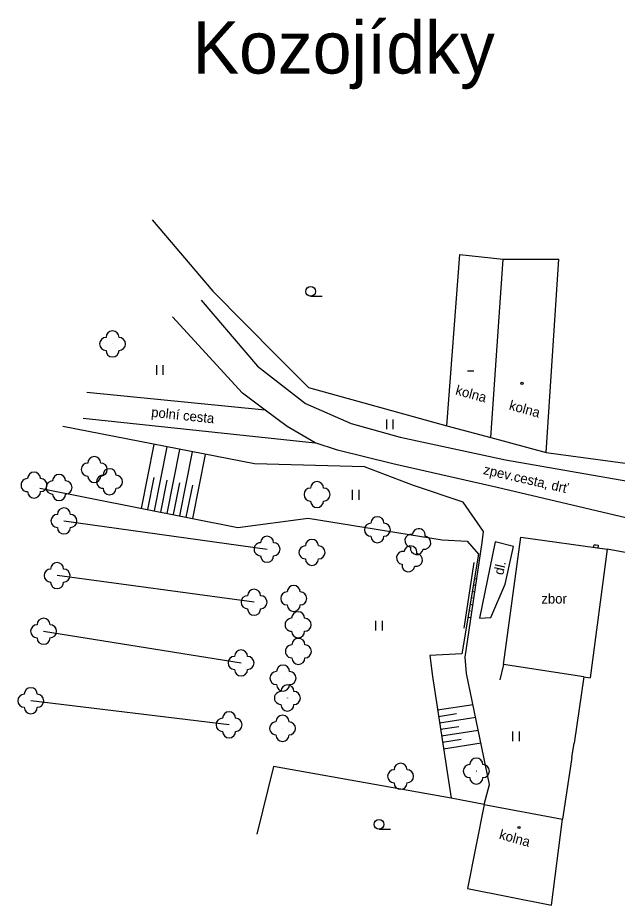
# Model space of a CAD drawing. Extents: x -544674 to -541478, y -1199076 to -1195527.
# Drawn here: x -543930.8 to -543884.8, y -1197382.1 to -1197313.9 of the extents above; entities that cross this region are included whole.
import ezdxf

# ---------------------------------------------------------------- set-up
doc = ezdxf.new("R2010")
doc.units = 0
for name, color, linetype in [('BUDOVY_MĚŘ', 7, 'Continuous'), ('BUDOVY_NEMĚŘ', 7, 'Continuous'), ('NÁZVY_SÍDEL_JEDNOTKY', 7, 'Continuous'), ('OBVOD_PILÍŘE', 7, 'Continuous'), ('POMOC_POPIS', 7, 'Continuous'), ('ROZHRANÍ_PLOCH', 7, 'Continuous'), ('VÝŠKOPIS', 7, 'Continuous'), ('ZELEŇ', 7, 'Continuous'), ('ZN_BUDOV', 7, 'Continuous'), ('ZN_DOPLŇKOVÉ', 7, 'Continuous'), ('ZN_KULTUR', 7, 'Continuous')]:
    doc.layers.add(name, color=color, linetype=linetype)

msp = doc.modelspace()

# ---------------------------------------------------------------- linework, layer by layer
at = {"layer": 'BUDOVY_MĚŘ'}
for points in [[(-543897.87, -1197345.26), (-543894.49, -1197346.15)], [(-543894.49, -1197346.15), (-543890.24, -1197347.31)], [(-543893.51, -1197363.58), (-543892.19, -1197353.8), (-543885.56, -1197354.73)], [(-543885.56, -1197354.73), (-543886.86, -1197364.61)], [(-543887.36, -1197364.53), (-543893.51, -1197363.58)], [(-543887.36, -1197364.53), (-543886.86, -1197364.61)], [(-543895.01, -1197374.32), (-543888.98, -1197375.44)]]:
    msp.add_lwpolyline(points, dxfattribs=at)
at = {"layer": 'BUDOVY_NEMĚŘ'}
for points in [[(-543897.87, -1197345.26), (-543896.87, -1197332.11)], [(-543896.87, -1197332.11), (-543893.55, -1197332.47)], [(-543894.49, -1197346.15), (-543893.55, -1197332.47)], [(-543893.55, -1197332.47), (-543889.26, -1197332.45)], [(-543890.24, -1197347.31), (-543889.26, -1197332.45)], [(-543895.01, -1197374.32), (-543896.29, -1197380.78), (-543889.83, -1197382.06), (-543888.98, -1197375.44)]]:
    msp.add_lwpolyline(points, dxfattribs=at)
at = {"layer": 'OBVOD_PILÍŘE'}
msp.add_lwpolyline([(-543886.41, -1197354.4), (-543886.25, -1197354.42), (-543886.28, -1197354.64), (-543886.6, -1197354.6), (-543886.57, -1197354.38), (-543886.41, -1197354.4)], dxfattribs=at)
at = {"layer": 'ROZHRANÍ_PLOCH'}
for points in [[(-543916.72, -1197335.6), (-543912.4, -1197340.67), (-543908.7, -1197343.54), (-543905.2, -1197345.09), (-543901.45, -1197346.13), (-543893.37, -1197347.87), (-543883.39, -1197349.61), (-543879.4, -1197350.37)], [(-543911.81, -1197344.06), (-543913.54, -1197342.76), (-543918.9, -1197336.89)], [(-543911.81, -1197344.06), (-543925.49, -1197342.71)], [(-543907.96, -1197346.55), (-543910.11, -1197345.31), (-543911.81, -1197344.06)], [(-543925.75, -1197344.68), (-543907.96, -1197346.55)], [(-543879.77, -1197353.15), (-543883.7, -1197352.41), (-543893.99, -1197349.99), (-543902.01, -1197348.18), (-543906.24, -1197347.12), (-543907.96, -1197346.55)], [(-543895.37, -1197360.02), (-543894.48, -1197359.97), (-543893.4, -1197357.42), (-543892.75, -1197354.51), (-543894.16, -1197354.17), (-543895.37, -1197360.02)]]:
    msp.add_lwpolyline(points, dxfattribs=at)
at = {"layer": 'VÝŠKOPIS'}
for points in [[(-543895.01, -1197374.32), (-543894.58, -1197372.78), (-543896.35, -1197364.26), (-543896.46, -1197363.02), (-543895.16, -1197354.2), (-543895.04, -1197353.37), (-543896.61, -1197351.11), (-543900.41, -1197349.84), (-543904.19, -1197348.41), (-543912.63, -1197348.18), (-543927.31, -1197345.32)], [(-543921.28, -1197351.59), (-543920.31, -1197346.68)], [(-543920.3, -1197351.78), (-543919.33, -1197346.88)], [(-543919.32, -1197351.98), (-543918.35, -1197347.07)], [(-543918.34, -1197352.17), (-543917.37, -1197347.26)], [(-543917.36, -1197352.36), (-543916.38, -1197347.45)], [(-543920.79, -1197351.68), (-543920.31, -1197349.23)], [(-543929.08, -1197350.04), (-543913.9, -1197353.05), (-543908.51, -1197352.34), (-543898.22, -1197354.01), (-543896.31, -1197354.12), (-543895.44, -1197355.11), (-543896.71, -1197362.76), (-543899.18, -1197362.88), (-543898.97, -1197364.51), (-543897.53, -1197373.85)], [(-543919.81, -1197351.88), (-543919.33, -1197349.42)], [(-543918.83, -1197352.07), (-543918.34, -1197349.62)], [(-543917.85, -1197352.27), (-543917.36, -1197349.81)], [(-543895.83, -1197357.47), (-543895.74, -1197357.49)], [(-543895.75, -1197356.98), (-543895.57, -1197357.01)], [(-543895.91, -1197357.96), (-543895.72, -1197358)], [(-543896, -1197358.46), (-543895.89, -1197358.47)], [(-543896.16, -1197359.44), (-543896.05, -1197359.46)], [(-543896.08, -1197358.95), (-543895.86, -1197358.99)], [(-543896.24, -1197359.94), (-543896.01, -1197359.97)], [(-543898.57, -1197367.07), (-543895.85, -1197366.65)], [(-543898.5, -1197367.56), (-543897.12, -1197367.35)], [(-543898.42, -1197368.06), (-543895.65, -1197367.63)], [(-543898.35, -1197368.55), (-543896.95, -1197368.34)], [(-543898.27, -1197369.05), (-543895.45, -1197368.61)], [(-543898.19, -1197369.54), (-543896.77, -1197369.32)], [(-543898.12, -1197370.04), (-543895.24, -1197369.59)]]:
    msp.add_lwpolyline(points, dxfattribs=at)
at = {"layer": 'ZELEŇ'}
for points in [[(-543927.24, -1197352.56), (-543911.65, -1197354.73)], [(-543912.65, -1197358.8), (-543927.76, -1197356.75)], [(-543928.8, -1197361.03), (-543913.65, -1197363.46)], [(-543914.57, -1197368.21), (-543929.78, -1197366.36)]]:
    msp.add_lwpolyline(points, dxfattribs=at)
for centre in [(-543923.51, -1197338.97), (-543924.91, -1197348.61), (-543929.53, -1197349.81), (-543927.61, -1197349.99), (-543923.74, -1197349.55), (-543907.82, -1197350.53), (-543927.24, -1197352.56), (-543903.19, -1197353.23), (-543900.09, -1197354.15), (-543911.65, -1197354.73), (-543908.21, -1197354.97), (-543900.73, -1197355.47), (-543927.76, -1197356.75), (-543912.65, -1197358.8), (-543909.61, -1197358.51), (-543909.27, -1197360.53), (-543928.8, -1197361.03), (-543909.25, -1197362.57), (-543913.65, -1197363.46), (-543910.43, -1197364.62), (-543929.78, -1197366.36), (-543910.09, -1197366.15), (-543914.57, -1197368.21), (-543910.47, -1197368.48), (-543895.6, -1197371.76), (-543901.41, -1197372.16)]:
    msp.add_circle(centre, 0.0005, dxfattribs=at)
for centre, start, end in [((-543924.01, -1197338.97), 89.99999, 269.99999), ((-543923.51, -1197338.47), 0, 179.99999), ((-543923.01, -1197338.97), 270, 89.99999), ((-543923.51, -1197339.47), 179.99999, 359.99999), ((-543924.91, -1197348.11), 360, 179.99999), ((-543925.41, -1197348.61), 90, 269.99999), ((-543924.41, -1197348.61), 270, 90), ((-543923.74, -1197349.05), 359.99998, 179.99998), ((-543930.03, -1197349.81), 89.99998, 269.99998), ((-543929.53, -1197349.31), 359.99998, 179.99998), ((-543929.03, -1197349.81), 269.99998, 89.99997), ((-543927.61, -1197349.49), 360, 179.99999), ((-543924.91, -1197349.11), 180, 360), ((-543924.24, -1197349.55), 89.99998, 269.99998), ((-543923.24, -1197349.55), 269.99998, 89.99997), ((-543928.11, -1197349.99), 90, 269.99999), ((-543927.11, -1197349.99), 270, 90), ((-543923.74, -1197350.05), 179.99998, 359.99997), ((-543908.32, -1197350.53), 89.99999, 269.99999), ((-543907.82, -1197350.03), 0, 179.99999), ((-543907.32, -1197350.53), 270, 89.99999), ((-543929.53, -1197350.31), 179.99998, 359.99997), ((-543927.61, -1197350.49), 180, 360), ((-543907.82, -1197351.03), 179.99999, 359.99999), ((-543927.74, -1197352.56), 90, 269.99999), ((-543927.24, -1197352.06), 360, 179.99999), ((-543926.74, -1197352.56), 270, 90), ((-543903.69, -1197353.23), 90, 269.99999), ((-543903.19, -1197352.73), 360, 179.99999), ((-543902.69, -1197353.23), 270, 90), ((-543927.24, -1197353.06), 180, 360), ((-543900.012, -1197353.656), 351.04001, 171.04001), ((-543911.65, -1197354.23), 359.99998, 179.99998), ((-543908.21, -1197354.47), 359.99998, 179.99998), ((-543903.19, -1197353.73), 180, 360), ((-543900.584, -1197354.072), 81.04001, 261.04), ((-543899.596, -1197354.228), 261.04001, 81.04001), ((-543912.15, -1197354.73), 89.99998, 269.99998), ((-543911.15, -1197354.73), 269.99998, 89.99997), ((-543908.71, -1197354.97), 89.99998, 269.99998), ((-543907.71, -1197354.97), 269.99998, 89.99997), ((-543900.652, -1197354.976), 351.04001, 171.04001), ((-543900.168, -1197354.644), 171.04001, 351.04), ((-543911.65, -1197355.23), 179.99998, 359.99997), ((-543908.21, -1197355.47), 179.99998, 359.99997), ((-543901.224, -1197355.392), 81.04001, 261.04), ((-543900.236, -1197355.548), 261.04001, 81.04001), ((-543927.76, -1197356.25), 360, 179.99999), ((-543900.808, -1197355.964), 171.04001, 351.04), ((-543928.26, -1197356.75), 90, 269.99999), ((-543927.26, -1197356.75), 270, 90), ((-543927.76, -1197357.25), 180, 360), ((-543909.61, -1197358.01), 360, 179.99999), ((-543912.65, -1197358.3), 360, 179.99999), ((-543910.11, -1197358.51), 90, 269.99999), ((-543909.11, -1197358.51), 270, 90), ((-543913.15, -1197358.8), 90, 269.99999), ((-543912.15, -1197358.8), 270, 90), ((-543912.65, -1197359.3), 180, 360), ((-543909.61, -1197359.01), 180, 360), ((-543909.27, -1197360.03), 359.99998, 179.99998), ((-543928.8, -1197360.53), 360, 179.99999), ((-543909.77, -1197360.53), 89.99998, 269.99998), ((-543908.77, -1197360.53), 269.99998, 89.99997), ((-543929.3, -1197361.03), 90, 269.99999), ((-543928.3, -1197361.03), 270, 90), ((-543928.8, -1197361.53), 180, 360), ((-543909.27, -1197361.03), 179.99998, 359.99997), ((-543909.25, -1197362.07), 359.99998, 179.99998), ((-543909.75, -1197362.57), 89.99998, 269.99998), ((-543908.75, -1197362.57), 269.99998, 89.99997), ((-543914.15, -1197363.46), 90, 269.99999), ((-543913.65, -1197362.96), 360, 179.99999), ((-543913.15, -1197363.46), 270, 90), ((-543910.43, -1197364.12), 360, 179.99999), ((-543909.25, -1197363.07), 179.99998, 359.99997), ((-543913.65, -1197363.96), 180, 360), ((-543910.93, -1197364.62), 90, 269.99999), ((-543909.93, -1197364.62), 270, 90), ((-543929.78, -1197365.86), 360, 179.99999), ((-543910.59, -1197366.15), 89.99998, 269.99998), ((-543910.43, -1197365.12), 180, 360), ((-543910.09, -1197365.65), 359.99998, 179.99998), ((-543909.59, -1197366.15), 269.99998, 89.99997), ((-543930.28, -1197366.36), 90, 269.99999), ((-543929.28, -1197366.36), 270, 90), ((-543929.78, -1197366.86), 180, 360), ((-543910.09, -1197366.65), 179.99998, 359.99997), ((-543915.07, -1197368.21), 89.99999, 269.99999), ((-543914.57, -1197367.71), 0, 179.99999), ((-543914.07, -1197368.21), 270, 89.99999), ((-543910.47, -1197367.98), 359.99998, 179.99998), ((-543910.97, -1197368.48), 89.99998, 269.99998), ((-543909.97, -1197368.48), 269.99998, 89.99997), ((-543914.57, -1197368.71), 179.99999, 359.99999), ((-543910.47, -1197368.98), 179.99998, 359.99997), ((-543901.41, -1197371.66), 360, 179.99999), ((-543895.6, -1197371.26), 360, 179.99999), ((-543901.91, -1197372.16), 90, 269.99999), ((-543900.91, -1197372.16), 270, 90), ((-543896.1, -1197371.76), 90, 269.99999), ((-543895.1, -1197371.76), 270, 90), ((-543895.6, -1197372.26), 180, 360), ((-543901.41, -1197372.66), 180, 360)]:
    msp.add_arc(centre, 0.5, start, end, dxfattribs=at)
at = {"layer": 'ZN_BUDOV'}
msp.add_line((-543896.28, -1197341.03), (-543895.78, -1197341.03), dxfattribs=at)
for centre in [(-543892.09, -1197341.99), (-543892.33, -1197376.09)]:
    msp.add_circle(centre, 0.0875, dxfattribs=at)
at = {"layer": 'ZN_DOPLŇKOVÉ'}
for points in [[(-543920.48, -1197329.44), (-543915.81, -1197334.92), (-543910.89, -1197339.9)], [(-543910.89, -1197339.9), (-543908.48, -1197342.32)], [(-543908.48, -1197342.32), (-543897.87, -1197345.26)], [(-543890.24, -1197347.31), (-543882.3, -1197348.39), (-543874.25, -1197349.54)], [(-543882.93, -1197355.22), (-543885.56, -1197354.73)], [(-543896.53, -1197360.78), (-543895.76, -1197355.75)], [(-543893.51, -1197363.58), (-543893.8, -1197364.76)], [(-543887.36, -1197364.53), (-543888.09, -1197369.63)], [(-543888.28, -1197370.72), (-543888.09, -1197369.63)], [(-543888.28, -1197370.72), (-543888.98, -1197375.44)], [(-543897.53, -1197373.85), (-543911.16, -1197371.4), (-543912.43, -1197376.6)], [(-543895.01, -1197374.32), (-543897.53, -1197373.85)]]:
    msp.add_lwpolyline(points, dxfattribs=at)
at = {"layer": 'ZN_KULTUR'}
for p, q in [((-543908.31, -1197335.315), (-543907.435, -1197335.315)), ((-543920.12, -1197341.345), (-543920.12, -1197340.595)), ((-543919.62, -1197341.345), (-543919.62, -1197340.595)), ((-543902.47, -1197345.515), (-543902.47, -1197344.765)), ((-543901.97, -1197345.515), (-543901.97, -1197344.765)), ((-543905.09, -1197350.925), (-543905.09, -1197350.175)), ((-543904.59, -1197350.925), (-543904.59, -1197350.175)), ((-543903.31, -1197360.965), (-543903.31, -1197360.215)), ((-543902.81, -1197360.965), (-543902.81, -1197360.215)), ((-543892.79, -1197369.465), (-543892.79, -1197368.715)), ((-543892.29, -1197369.465), (-543892.29, -1197368.715)), ((-543903.06, -1197376.225), (-543902.185, -1197376.225))]:
    msp.add_line(p, q, dxfattribs=at)
for centre in [(-543908.31, -1197334.94), (-543903.06, -1197375.85)]:
    msp.add_circle(centre, 0.375, dxfattribs=at)

# ---------------------------------------------------------------- texts
at = {"layer": 'NÁZVY_SÍDEL_JEDNOTKY'}
msp.add_text('Kozojídky', height=4, dxfattribs=at).set_placement((-543917.37, -1197318.21))
at = {"layer": 'POMOC_POPIS'}
for s, rotation, p in [('kolna', 344.73003, (-543897.25, -1197342.84)), ('polní cesta', 354.00003, (-543920.57, -1197344.56)), ('kolna', 344.73003, (-543893.14, -1197344)), ('zpev.cesta, drť', 347.02002, (-543895.11, -1197348.95)), ('dl.', 77.40998, (-543893.55, -1197356.75)), ('kolna', 344.73003, (-543893.9, -1197376.95))]:
    msp.add_text(s, height=0.75, rotation=rotation, dxfattribs=at).set_placement(p)
msp.add_text('zbor', height=0.75, dxfattribs=at).set_placement((-543890.61, -1197358.9))

doc.saveas('drawing.dxf')
